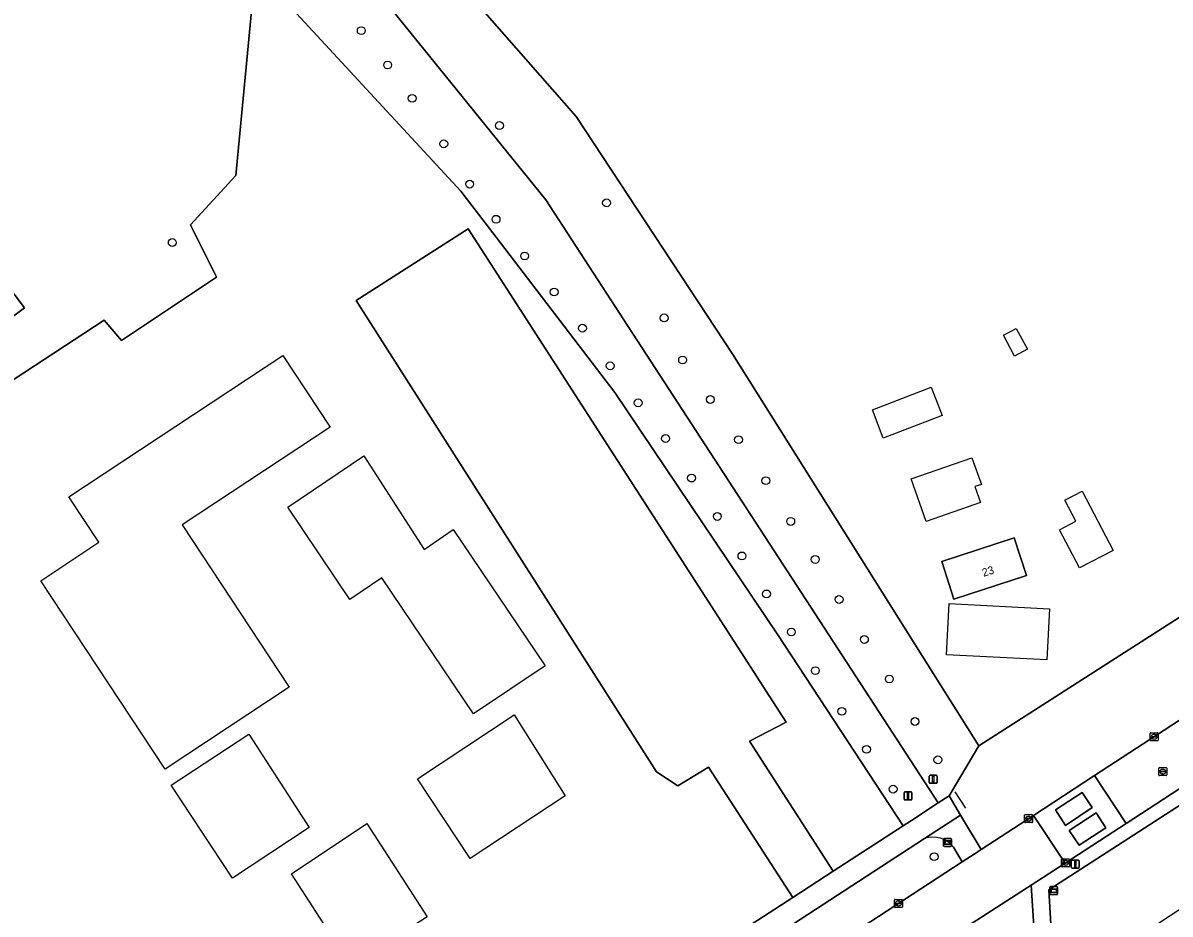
# Model space of a CAD drawing. Extents: x 159451 to 160664, y 388402 to 389723.
# Drawn here: x 159762 to 159905.3, y 389267.3 to 389378.7 of the extents above; entities that cross this region are included whole.
import ezdxf

# ---------------------------------------------------------------- set-up
doc = ezdxf.new("R2010")
doc.units = 0
for name, color, linetype in [('IMGEO_Afsluitpaal', 7, 'Continuous'), ('IMGEO_Berm_groen', 7, 'Continuous'), ('IMGEO_Berm_open', 7, 'Continuous'), ('IMGEO_Boom', 7, 'Continuous'), ('IMGEO_Fietspad_gesloten', 7, 'Continuous'), ('IMGEO_Fietspad_open', 7, 'Continuous'), ('IMGEO_Groenvoorziening', 7, 'Continuous'), ('IMGEO_Hek', 7, 'Continuous'), ('IMGEO_Kolk', 7, 'Continuous'), ('IMGEO_Lichtmast', 7, 'Continuous'), ('IMGEO_Loofbos', 7, 'Continuous'), ('IMGEO_Muur', 7, 'Continuous'), ('IMGEO_Pand', 7, 'Continuous'), ('IMGEO_Pand_nummerreeks', 7, 'Continuous'), ('IMGEO_Pand_vergunning_verleend', 7, 'Continuous'), ('IMGEO_Parkeervlak_halfverhard', 7, 'Continuous'), ('IMGEO_Rijbaan_lokaal_gesloten', 7, 'Continuous'), ('IMGEO_Rijbaan_lokaal_open', 7, 'Continuous'), ('IMGEO_Rioolput', 7, 'Continuous'), ('IMGEO_Straatnaambord', 7, 'Continuous'), ('IMGEO_Wegwijzer', 7, 'Continuous')]:
    doc.layers.add(name, color=color, linetype=linetype)

msp = doc.modelspace()

# ---------------------------------------------------------------- linework, layer by layer
at = {"layer": 'IMGEO_Afsluitpaal'}
for p, q in [((159875.21, 389283.72), (159875.21, 389284.52)), ((159875.21, 389284.52), (159875.21, 389283.72)), ((159875.31, 389284.62), (159876.1, 389284.62)), ((159876.1, 389284.62), (159875.31, 389284.62)), ((159876.2, 389284.52), (159876.2, 389283.72)), ((159876.2, 389283.72), (159876.2, 389284.52)), ((159876.1, 389283.62), (159875.31, 389283.62)), ((159875.31, 389283.62), (159876.1, 389283.62)), ((159872.06, 389281.64), (159872.06, 389282.44)), ((159872.06, 389282.44), (159872.06, 389281.64)), ((159872.16, 389282.54), (159872.95, 389282.54)), ((159872.95, 389282.54), (159872.16, 389282.54)), ((159872.95, 389281.54), (159872.16, 389281.54)), ((159872.16, 389281.54), (159872.95, 389281.54)), ((159873.05, 389282.44), (159873.05, 389281.64)), ((159873.05, 389281.64), (159873.05, 389282.44))]:
    msp.add_line(p, q, dxfattribs=at)
for points in [[(159875.63, 389284.49), (159875.78, 389284.49), (159875.78, 389283.74), (159875.63, 389283.74), (159875.63, 389284.49)], [(159872.48, 389282.41), (159872.63, 389282.41), (159872.63, 389281.66), (159872.48, 389281.66), (159872.48, 389282.41)]]:
    msp.add_lwpolyline(points, dxfattribs=at)
for centre, start, end in [((159875.31, 389284.52), 90, 180), ((159875.31, 389284.52), 90, 180), ((159876.1, 389284.52), 0, 90), ((159876.1, 389284.52), 360, 90), ((159875.31, 389283.72), 180, 270), ((159875.31, 389283.72), 180, 270), ((159876.1, 389283.72), 270, 0), ((159876.1, 389283.72), 270, 0), ((159872.16, 389282.44), 90, 180), ((159872.16, 389282.44), 90, 180), ((159872.16, 389281.64), 180, 270), ((159872.16, 389281.64), 180, 270), ((159872.95, 389282.44), 0, 90), ((159872.95, 389282.44), 360, 90), ((159872.95, 389281.64), 270, 0), ((159872.95, 389281.64), 270, 0)]:
    msp.add_arc(centre, 0.1, start, end, dxfattribs=at)
at = {"layer": 'IMGEO_Berm_groen'}
for points in [[(159986.35, 389343.16), (160000, 389351.61), (160005.85, 389355.23), (160011.54, 389358.23), (160022.23, 389362.94), (160022.75, 389363.16), (160024.31, 389363.83), (160036.11, 389368.42), (160036.17, 389368.93), (160036.04, 389370.93), (160038.03, 389371.1), (160037.55, 389374.64), (160039.62, 389374.92), (160039.49, 389376.11), (160004.13, 389366.97), (159881.39, 389288.32), (159877.68, 389282.04), (159879.11, 389279.64), (159881.68, 389275.33), (159888.24, 389279.61), (159895.87, 389284.58), (159930.8, 389307.35)], [(159994.26, 389325.91), (160002.52, 389330.32), (160007.31, 389333.3), (160003.3, 389339.49), (160002.81, 389340.25), (160000.75, 389338.88), (159999.17, 389341.19), (159962.36, 389317.3), (159918.72, 389288.76), (159890.17, 389270.29), (159890.42, 389265.99), (159893.33, 389261.45), (159891.48, 389260.21), (159891.87, 389259.62), (159900.41, 389263.84)]]:
    msp.add_lwpolyline(points, close=True, dxfattribs=at)
for points in [[(159874.62, 389276.71), (159833.66, 389250), (159832.31, 389249.12), (159833.35, 389247.52), (159837.08, 389246.17), (159837.72, 389246.59), (159838.01, 389246.78), (159842.33, 389249.6), (159842.95, 389250), (159855.43, 389258.17), (159879.33, 389273.81)], [(159879.33, 389273.81), (159878.24, 389275.65)]]:
    msp.add_lwpolyline(points, dxfattribs=at)
msp.add_arc((159875.68, 389273.6), 3.28, 38.73, 108.7521, dxfattribs=at)
at = {"layer": 'IMGEO_Berm_open'}
msp.add_lwpolyline([(159998.77, 389342.96), (159973.82, 389326.76), (159947.89, 389309.89), (159906.38, 389282.87), (159899.83, 389278.61), (159892.21, 389273.65), (159887.95, 389270.88), (159888.32, 389265.1), (159891.48, 389260.21), (159893.33, 389261.45), (159890.42, 389265.99), (159890.17, 389270.29), (159918.72, 389288.76), (159962.36, 389317.3), (159999.17, 389341.19)], dxfattribs=at)
at = {"layer": 'IMGEO_Boom'}
for centre in [(159804.26, 389377.7), (159807.56, 389373.4), (159810.62, 389369.23), (159821.52, 389365.83), (159814.57, 389363.55), (159817.8, 389358.51), (159834.9, 389356.17), (159821.1, 389354.12), (159780.65, 389351.21), (159824.67, 389349.53), (159828.35, 389345.02), (159842.1, 389341.79), (159831.89, 389340.5), (159835.35, 389335.8), (159844.4, 389336.53), (159838.85, 389331.17), (159847.86, 389331.59), (159842.27, 389326.71), (159851.39, 389326.57), (159845.52, 389321.77), (159854.79, 389321.44), (159848.74, 389316.97), (159857.91, 389316.35), (159851.81, 389312.04), (159860.96, 389311.6), (159854.88, 389307.29), (159863.95, 389306.6), (159857.99, 389302.53), (159867.11, 389301.6), (159860.98, 389297.7), (159870.23, 389296.66), (159864.29, 389292.61), (159873.43, 389291.34), (159867.38, 389287.86), (159876.29, 389286.55), (159870.7, 389282.89), (159875.82, 389274.44)]:
    msp.add_circle(centre, 0.489, dxfattribs=at)
at = {"layer": 'IMGEO_Fietspad_gesloten'}
msp.add_lwpolyline([(159833.66, 389250), (159874.62, 389276.71), (159879.11, 389279.64), (159877.68, 389282.04), (159876.34, 389281.17), (159872.99, 389278.98), (159871.96, 389278.31), (159863.19, 389272.62), (159858.15, 389269.35), (159792.67, 389226.89)], dxfattribs=at)
at = {"layer": 'IMGEO_Fietspad_open'}
msp.add_lwpolyline([(159878.24, 389275.65), (159879.33, 389273.81), (159880.95, 389274.86), (159881.68, 389275.33), (159879.11, 389279.64), (159874.62, 389276.71)], dxfattribs=at)
msp.add_arc((159875.68, 389273.6), 3.28, 38.73, 108.7521, dxfattribs=at)
at = {"layer": 'IMGEO_Groenvoorziening'}
for points in [[(159811.91, 389388.9), (159831.1, 389366.95), (159850.68, 389337.23), (159874.34, 389299.54), (159881.39, 389288.32), (160004.13, 389366.97), (160039.49, 389376.11), (160038.58, 389384.31)], [(159858.15, 389269.35), (159847.62, 389285.65), (159843.81, 389283.3), (159841.12, 389285.04), (159803.63, 389343.97), (159817.62, 389352.91), (159857.34, 389291.26), (159852.77, 389288.88), (159863.19, 389272.62), (159871.96, 389278.31), (159856.3, 389302.19), (159835.93, 389332.46), (159821.1, 389351.87), (159816.71, 389357.62), (159791.04, 389385.41), (159788.61, 389359.57), (159782.92, 389353.41), (159786.17, 389346.9), (159774.32, 389338.96), (159772.15, 389341.51), (159744.65, 389323.51), (159741.65, 389327.63), (159762.21, 389343.03), (159732.27, 389382.65)], [(159691.58, 389172.29), (159696.14, 389164.01), (159699.25, 389166.04), (159708.79, 389172.23), (159708.9, 389172.15), (159709.02, 389172.23), (159711.83, 389174.02), (159716.67, 389177.13), (159717.81, 389177.93), (159784.33, 389221.43), (159782.97, 389223.53), (159785.89, 389225.49), (159787.28, 389223.36), (159792.67, 389226.89), (159858.15, 389269.35)]]:
    msp.add_lwpolyline(points, dxfattribs=at)
msp.add_lwpolyline([(159887.34, 389309.58), (159878.29, 389306.65), (159876.78, 389311.33), (159885.8, 389314.28)], close=True, dxfattribs=at)
at = {"layer": 'IMGEO_Hek'}
msp.add_lwpolyline([(159878.4, 389282.57), (159879.76, 389280.52)], dxfattribs=at)
at = {"layer": 'IMGEO_Kolk'}
for p, q in [((159902.81, 389289.01), (159902.81, 389289.86)), ((159902.88, 389289.93), (159903.74, 389289.93)), ((159903.74, 389288.93), (159902.88, 389288.93)), ((159903.07, 389289.43), (159903.07, 389289.44)), ((159903.11, 389289.48), (159903.51, 389289.48)), ((159903.51, 389289.39), (159903.11, 389289.39)), ((159903.32, 389289.15), (159903.29, 389289.15)), ((159903.3, 389289.71), (159903.32, 389289.71)), ((159903.55, 389289.44), (159903.55, 389289.43)), ((159903.81, 389289.86), (159903.81, 389289.01)), ((159887.12, 389278.78), (159887.12, 389279.63)), ((159887.19, 389279.7), (159888.05, 389279.7)), ((159888.05, 389278.7), (159887.19, 389278.7)), ((159887.38, 389279.2), (159887.38, 389279.21)), ((159887.42, 389279.25), (159887.82, 389279.25)), ((159887.82, 389279.16), (159887.42, 389279.16)), ((159887.63, 389278.92), (159887.6, 389278.92)), ((159887.61, 389279.48), (159887.63, 389279.48)), ((159887.86, 389279.21), (159887.86, 389279.2)), ((159888.12, 389279.63), (159888.12, 389278.78)), ((159891.73, 389273.25), (159891.73, 389274.1)), ((159891.8, 389274.18), (159892.66, 389274.18)), ((159892.66, 389273.18), (159891.8, 389273.18)), ((159891.99, 389273.67), (159891.99, 389273.68)), ((159892.03, 389273.72), (159892.43, 389273.72)), ((159892.43, 389273.63), (159892.03, 389273.63)), ((159892.24, 389273.4), (159892.21, 389273.4)), ((159892.22, 389273.96), (159892.24, 389273.96)), ((159892.47, 389273.68), (159892.47, 389273.67)), ((159892.73, 389274.1), (159892.73, 389273.25)), ((159870.87, 389268.17), (159870.87, 389269.03)), ((159870.94, 389269.1), (159871.79, 389269.1)), ((159871.13, 389268.59), (159871.13, 389268.61)), ((159871.17, 389268.64), (159871.57, 389268.64)), ((159871.36, 389268.88), (159871.38, 389268.88)), ((159871.61, 389268.61), (159871.61, 389268.59)), ((159871.87, 389269.03), (159871.87, 389268.17)), ((159871.79, 389268.1), (159870.94, 389268.1)), ((159871.56, 389268.56), (159871.17, 389268.56)), ((159871.38, 389268.32), (159871.35, 389268.32))]:
    msp.add_line(p, q, dxfattribs=at)
for points in [[(159902.81, 389289.01), (159902.81, 389289.86)], [(159902.88, 389289.93), (159903.74, 389289.93)], [(159903.74, 389288.93), (159902.88, 389288.93)], [(159903.81, 389289.86), (159903.81, 389289.01)], [(159887.12, 389278.78), (159887.12, 389279.63)], [(159887.19, 389279.7), (159888.05, 389279.7)], [(159888.05, 389278.7), (159887.19, 389278.7)], [(159888.12, 389279.63), (159888.12, 389278.78)], [(159891.73, 389273.25), (159891.73, 389274.1)], [(159891.8, 389274.18), (159892.66, 389274.18)], [(159892.66, 389273.18), (159891.8, 389273.18)], [(159892.73, 389274.1), (159892.73, 389273.25)], [(159870.87, 389268.17), (159870.87, 389269.03)], [(159870.94, 389269.1), (159871.79, 389269.1)], [(159871.87, 389269.03), (159871.87, 389268.17)], [(159871.79, 389268.1), (159870.94, 389268.1)]]:
    msp.add_lwpolyline(points, dxfattribs=at)
for centre, radius, start, end in [((159902.89, 389289.86), 0.0765, 91.552, 178.448), ((159902.89, 389289.86), 0.0765, 91.552, 178.448), ((159902.89, 389289.01), 0.0765, 181.552, 268.448), ((159902.89, 389289.01), 0.0765, 181.552, 268.448), ((159903.11, 389289.44), 0.0403, 85.8775, 175.7526), ((159903.1, 389289.43), 0.0366, 178.938, 274.7102), ((159903.51, 389289.44), 0.0386, 1.7309, 96.639), ((159903.51, 389289.43), 0.043, 264.8664, 352.4533), ((159903.73, 389289.86), 0.0765, 1.552, 88.448), ((159903.73, 389289.86), 0.0765, 1.552, 88.448), ((159903.73, 389289.01), 0.0765, 271.552, 358.448), ((159903.73, 389289.01), 0.0765, 271.552, 358.448), ((159887.2, 389279.63), 0.0765, 91.552, 178.448), ((159887.2, 389279.63), 0.0765, 91.552, 178.448), ((159887.2, 389278.78), 0.0765, 181.552, 268.448), ((159887.2, 389278.78), 0.0765, 181.552, 268.448), ((159887.42, 389279.21), 0.0403, 85.8775, 175.7526), ((159887.41, 389279.2), 0.0366, 178.938, 274.7102), ((159887.82, 389279.21), 0.0386, 1.7309, 96.639), ((159887.82, 389279.2), 0.043, 264.8664, 352.4533), ((159888.04, 389279.63), 0.0765, 1.552, 88.448), ((159888.04, 389279.63), 0.0765, 1.552, 88.448), ((159888.04, 389278.78), 0.0765, 271.552, 358.448), ((159888.04, 389278.78), 0.0765, 271.552, 358.448), ((159891.81, 389274.1), 0.0765, 91.552, 178.448), ((159891.81, 389274.1), 0.0765, 91.552, 178.448), ((159891.81, 389273.25), 0.0765, 181.552, 268.448), ((159891.81, 389273.25), 0.0765, 181.552, 268.448), ((159892.03, 389273.68), 0.0403, 85.8775, 175.7526), ((159892.02, 389273.67), 0.0366, 178.938, 274.7102), ((159892.43, 389273.68), 0.0386, 1.7309, 96.639), ((159892.43, 389273.68), 0.043, 264.8664, 352.4533), ((159892.65, 389274.1), 0.0765, 1.552, 88.448), ((159892.65, 389274.1), 0.0765, 1.552, 88.448), ((159892.65, 389273.25), 0.0765, 271.552, 358.448), ((159892.65, 389273.25), 0.0765, 271.552, 358.448), ((159870.94, 389269.02), 0.0765, 91.552, 178.448), ((159870.94, 389269.02), 0.0765, 91.552, 178.448), ((159871.17, 389268.6), 0.0403, 85.8775, 175.7526), ((159871.57, 389268.6), 0.0386, 1.7309, 96.639), ((159871.79, 389269.02), 0.0765, 1.552, 88.448), ((159871.79, 389269.02), 0.0765, 1.552, 88.448), ((159870.94, 389268.17), 0.0765, 181.552, 268.448), ((159870.94, 389268.17), 0.0765, 181.552, 268.448), ((159871.16, 389268.59), 0.0366, 178.938, 274.7102), ((159871.57, 389268.6), 0.043, 264.8664, 352.4533), ((159871.79, 389268.17), 0.0765, 271.552, 358.448), ((159871.79, 389268.17), 0.0765, 271.552, 358.448)]:
    msp.add_arc(centre, radius, start, end, dxfattribs=at)
for centre, major_axis, ratio, start_param, end_param in [((159903.3, 389289.43), (-0.387, 0.002), 0.722429, 4.712389, 7.853982), ((159903.32, 389289.43), (-0.39, 0.002), 0.717154, 1.570796, 4.712389), ((159887.61, 389279.2), (-0.387, 0.002), 0.722429, 4.712389, 7.853982), ((159887.63, 389279.2), (-0.39, 0.002), 0.717154, 1.570796, 4.712389), ((159892.22, 389273.68), (-0.387, 0.002), 0.722429, 4.712389, 7.853982), ((159892.24, 389273.68), (-0.39, 0.002), 0.717154, 1.570796, 4.712389), ((159871.35, 389268.6), (-0.387, 0.002), 0.722429, 4.712389, 7.853982), ((159871.38, 389268.6), (-0.39, 0.002), 0.717154, 1.570796, 4.712389)]:
    msp.add_ellipse(centre, major_axis=major_axis, ratio=ratio, start_param=start_param, end_param=end_param, dxfattribs=at)
at = {"layer": 'IMGEO_Lichtmast'}
for p, q in [((159892.96, 389273.12), (159892.96, 389273.91)), ((159892.96, 389273.91), (159892.96, 389273.12)), ((159893.06, 389274.01), (159893.85, 389274.01)), ((159893.85, 389274.01), (159893.06, 389274.01)), ((159893.85, 389273.02), (159893.06, 389273.02)), ((159893.06, 389273.02), (159893.85, 389273.02)), ((159893.95, 389273.91), (159893.95, 389273.12)), ((159893.95, 389273.12), (159893.95, 389273.91))]:
    msp.add_line(p, q, dxfattribs=at)
msp.add_lwpolyline([(159893.38, 389273.89), (159893.53, 389273.89), (159893.53, 389273.14), (159893.38, 389273.14), (159893.38, 389273.89)], dxfattribs=at)
for centre, start, end in [((159893.06, 389273.91), 90, 180), ((159893.06, 389273.91), 90, 180), ((159893.06, 389273.12), 180, 270), ((159893.06, 389273.12), 180, 270), ((159893.85, 389273.91), 0, 90), ((159893.85, 389273.91), 360, 90), ((159893.85, 389273.12), 270, 0), ((159893.85, 389273.12), 270, 0)]:
    msp.add_arc(centre, 0.1, start, end, dxfattribs=at)
at = {"layer": 'IMGEO_Loofbos'}
msp.add_lwpolyline([(159831.1, 389366.95), (159811.91, 389388.9), (159794.48, 389423.34), (159795.07, 389420.92), (159794.97, 389418.19), (159794.05, 389415.51), (159792.55, 389413.25), (159790.3, 389411.43), (159788, 389410.57), (159785.15, 389410.62), (159782.84, 389411.56), (159827.32, 389356.54), (159838.14, 389339.9), (159876.34, 389281.17), (159877.68, 389282.04), (159881.39, 389288.32), (159874.34, 389299.54), (159850.68, 389337.23)], close=True, dxfattribs=at)
msp.add_lwpolyline([(159732.27, 389382.65), (159762.21, 389343.03), (159741.65, 389327.63), (159744.65, 389323.51), (159772.15, 389341.51), (159774.32, 389338.96), (159786.17, 389346.9), (159782.92, 389353.41), (159788.61, 389359.57), (159791.04, 389385.41), (159816.71, 389357.62), (159821.1, 389351.87), (159835.93, 389332.46), (159856.3, 389302.19), (159871.96, 389278.31), (159872.99, 389278.98), (159876.34, 389281.17), (159838.14, 389339.9), (159827.32, 389356.54), (159782.84, 389411.56)], dxfattribs=at)
at = {"layer": 'IMGEO_Muur'}
for points in [[(159881.39, 389288.32), (160004.13, 389366.97), (160039.49, 389376.11)], [(159850.68, 389337.23), (159874.34, 389299.54)], [(159874.34, 389299.54), (159881.39, 389288.32)]]:
    msp.add_lwpolyline(points, dxfattribs=at)
at = {"layer": 'IMGEO_Pand'}
msp.add_lwpolyline([(159885.8, 389314.28), (159876.78, 389311.33), (159878.29, 389306.65), (159887.34, 389309.58)], close=True, dxfattribs=at)
at = {"layer": 'IMGEO_Pand_vergunning_verleend'}
for points in [[(159884.47, 389339.62), (159886.07, 389340.48), (159887.47, 389337.87), (159885.87, 389337.01)], [(159764.21, 389308.94), (159771.49, 389313.75), (159767.73, 389319.44), (159794.48, 389337.1), (159800.39, 389328.15), (159781.87, 389315.92), (159795.27, 389295.63), (159779.76, 389285.39)], [(159868.11, 389330.31), (159875.47, 389333.15), (159876.84, 389329.61), (159869.47, 389326.77)], [(159795.07, 389318.14), (159804.57, 389324.54), (159812.1, 389312.86), (159815.76, 389315.33), (159827.23, 389298.31), (159818.29, 389292.28), (159806.84, 389309.28), (159802.85, 389306.6)], [(159872.96, 389321.68), (159880.55, 389324.32), (159881.72, 389320.98), (159880.92, 389320.7), (159881.61, 389318.73), (159874.81, 389316.36)], [(159891.49, 389315.32), (159893.52, 389316.37), (159892.15, 389319.02), (159894.31, 389320.14), (159898.17, 389312.7), (159893.98, 389310.53)], [(159877.37, 389299.69), (159877.7, 389306.08), (159890.24, 389305.44), (159889.91, 389299.04)], [(159811.27, 389284.16), (159823.36, 389292.16), (159829.75, 389282.07), (159817.85, 389274.2)], [(159780.53, 389283.37), (159790.22, 389289.77), (159797.74, 389278.09), (159788.19, 389271.78)], [(159795.56, 389272.29), (159804.94, 389278.6), (159812.5, 389266.93), (159803.01, 389260.78)]]:
    msp.add_lwpolyline(points, close=True, dxfattribs=at)
at = {"layer": 'IMGEO_Parkeervlak_halfverhard'}
msp.add_lwpolyline([(159817.62, 389352.91), (159803.63, 389343.97), (159841.12, 389285.04), (159843.81, 389283.3), (159847.62, 389285.65), (159858.15, 389269.35), (159863.19, 389272.62), (159852.77, 389288.88), (159857.34, 389291.26)], close=True, dxfattribs=at)
at = {"layer": 'IMGEO_Rijbaan_lokaal_gesloten'}
msp.add_lwpolyline([(159930.8, 389307.35), (159895.87, 389284.58), (159899.83, 389278.61), (159906.38, 389282.87)], dxfattribs=at)
for points in [[(159895.55, 389280.58), (159894.31, 389282.47), (159891, 389280.29), (159892.25, 389278.36)], [(159878.69, 389264.93), (159887.95, 389270.88), (159892.21, 389273.65), (159888.24, 389279.61), (159881.68, 389275.33), (159880.95, 389274.86), (159879.33, 389273.81), (159855.43, 389258.17), (159842.95, 389250), (159842.33, 389249.6), (159838.01, 389246.78), (159837.72, 389246.59), (159841.44, 389240.65), (159841.64, 389240.8), (159846.44, 389243.91), (159849.52, 389245.98), (159855.71, 389250)], [(159897.29, 389278.06), (159896.05, 389279.94), (159892.71, 389277.72), (159893.95, 389275.88)]]:
    msp.add_lwpolyline(points, close=True, dxfattribs=at)
at = {"layer": 'IMGEO_Rijbaan_lokaal_open'}
for points in [[(159888.24, 389279.61), (159892.21, 389273.65), (159899.83, 389278.61), (159895.87, 389284.58)], [(159892.25, 389278.36), (159891, 389280.29), (159894.31, 389282.47), (159895.55, 389280.58)], [(159893.95, 389275.88), (159892.71, 389277.72), (159896.05, 389279.94), (159897.29, 389278.06)], [(159888.32, 389265.1), (159887.95, 389270.88), (159878.69, 389264.93), (159883.73, 389262.3), (159886.8, 389257.67), (159887.08, 389257.25), (159888.52, 389254.99), (159892.94, 389257.95), (159891.87, 389259.62), (159891.48, 389260.21)]]:
    msp.add_lwpolyline(points, close=True, dxfattribs=at)
at = {"layer": 'IMGEO_Rioolput'}
for p, q in [((159903.89, 389284.66), (159903.89, 389285.51)), ((159903.96, 389285.58), (159904.82, 389285.58)), ((159904.82, 389284.58), (159903.96, 389284.58)), ((159904.15, 389285.08), (159904.15, 389285.09)), ((159904.19, 389285.13), (159904.59, 389285.13)), ((159904.58, 389285.04), (159904.19, 389285.04)), ((159904.4, 389284.8), (159904.37, 389284.8)), ((159904.38, 389285.36), (159904.4, 389285.36)), ((159904.63, 389285.09), (159904.63, 389285.08)), ((159904.89, 389285.51), (159904.89, 389284.66))]:
    msp.add_line(p, q, dxfattribs=at)
for points in [[(159903.89, 389284.66), (159903.89, 389285.51)], [(159903.96, 389285.58), (159904.82, 389285.58)], [(159904.82, 389284.58), (159903.96, 389284.58)], [(159904.89, 389285.51), (159904.89, 389284.66)]]:
    msp.add_lwpolyline(points, dxfattribs=at)
for centre, radius, start, end in [((159903.96, 389285.51), 0.0765, 91.552, 178.448), ((159903.96, 389285.51), 0.0765, 91.552, 178.448), ((159903.96, 389284.66), 0.0765, 181.552, 268.448), ((159903.96, 389284.66), 0.0765, 181.552, 268.448), ((159904.19, 389285.09), 0.0403, 85.8775, 175.7526), ((159904.18, 389285.08), 0.0366, 178.938, 274.7102), ((159904.59, 389285.08), 0.043, 264.8664, 352.4533), ((159904.59, 389285.09), 0.0386, 1.7309, 96.639), ((159904.81, 389285.51), 0.0765, 1.552, 88.448), ((159904.81, 389285.51), 0.0765, 1.552, 88.448), ((159904.81, 389284.66), 0.0765, 271.552, 358.448), ((159904.81, 389284.66), 0.0765, 271.552, 358.448)]:
    msp.add_arc(centre, radius, start, end, dxfattribs=at)
for centre, major_axis, ratio, start_param, end_param in [((159904.38, 389285.08), (-0.387, 0.002), 0.722429, 4.712389, 7.853982), ((159904.4, 389285.08), (-0.39, 0.002), 0.717154, 1.570796, 4.712389)]:
    msp.add_ellipse(centre, major_axis=major_axis, ratio=ratio, start_param=start_param, end_param=end_param, dxfattribs=at)
at = {"layer": 'IMGEO_Straatnaambord'}
for p, q in [((159877.01, 389275.81), (159877.01, 389276.61)), ((159877.01, 389276.61), (159877.01, 389275.81)), ((159877.11, 389276.71), (159877.9, 389276.71)), ((159877.9, 389276.71), (159877.11, 389276.71)), ((159878, 389276.61), (159878, 389275.81)), ((159878, 389275.81), (159878, 389276.61)), ((159877.9, 389275.71), (159877.11, 389275.71)), ((159877.11, 389275.71), (159877.9, 389275.71))]:
    msp.add_line(p, q, dxfattribs=at)
for points in [[(159877.12, 389276.45), (159877.9, 389276.45), (159877.9, 389275.98), (159877.12, 389275.98), (159877.12, 389276.45)], [(159877.18, 389276.38), (159877.18, 389276.05), (159877.84, 389276.05), (159877.84, 389276.38), (159877.18, 389276.38)]]:
    msp.add_lwpolyline(points, dxfattribs=at)
for centre, start, end in [((159877.11, 389276.61), 90, 180), ((159877.11, 389276.61), 90, 180), ((159877.11, 389275.81), 180, 270), ((159877.11, 389275.81), 180, 270), ((159877.9, 389276.61), 0, 90), ((159877.9, 389276.61), 360, 90), ((159877.9, 389275.81), 270, 0), ((159877.9, 389275.81), 270, 0)]:
    msp.add_arc(centre, 0.1, start, end, dxfattribs=at)
at = {"layer": 'IMGEO_Wegwijzer'}
for p, q in [((159890.26, 389269.8), (159890.26, 389270.6)), ((159890.26, 389270.6), (159890.26, 389269.8)), ((159890.36, 389270.7), (159891.15, 389270.7)), ((159891.15, 389270.7), (159890.36, 389270.7)), ((159891.25, 389270.6), (159891.25, 389269.8)), ((159891.25, 389269.8), (159891.25, 389270.6)), ((159891.15, 389269.7), (159890.36, 389269.7)), ((159890.36, 389269.7), (159891.15, 389269.7))]:
    msp.add_line(p, q, dxfattribs=at)
for points in [[(159890.37, 389270.43), (159891.15, 389270.43), (159891.15, 389269.96), (159890.37, 389269.96), (159890.37, 389270.43)], [(159890.43, 389270.36), (159890.43, 389270.03), (159891.09, 389270.03), (159891.09, 389270.36), (159890.43, 389270.36)]]:
    msp.add_lwpolyline(points, dxfattribs=at)
for centre, start, end in [((159890.36, 389270.6), 90, 180), ((159890.36, 389270.6), 90, 180), ((159891.15, 389270.6), 0, 90), ((159891.15, 389270.6), 360, 90), ((159890.36, 389269.8), 180, 270), ((159890.36, 389269.8), 180, 270), ((159891.15, 389269.8), 270, 0), ((159891.15, 389269.8), 270, 0)]:
    msp.add_arc(centre, 0.1, start, end, dxfattribs=at)

# ---------------------------------------------------------------- texts
at = {"layer": 'IMGEO_Pand_nummerreeks'}
msp.add_text('23', height=1, rotation=17.9278, dxfattribs=at).set_placement((159881.99, 389309.42))

doc.saveas('drawing.dxf')
